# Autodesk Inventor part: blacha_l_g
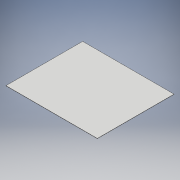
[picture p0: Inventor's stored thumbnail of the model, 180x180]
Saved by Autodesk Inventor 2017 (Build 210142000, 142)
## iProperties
Created: 2020-06
Part Number: blacha_l_g
Material: Generic
Document SubType Name: Modeling
Designer: WindowsX
Density: 1 g/cm^3
Appearance: Default
Author: WindowsX
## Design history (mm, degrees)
sketch "Szkic1"
  geometry: L1 (0, 0)-(1180, 0); L2 (1180, 0)-(1180, 990); L3 (1180, 990)-(0, 990); L4 (0, 990)-(0, 0)
  constraints: 8 end point, 2 parallel, 1 horizontal, 1 perpendicular
  dimensions: "d0" = 1180 distance of L2.end L3.end; "d1" = 990 distance of L1.start L3.end
extrude "Wyciągnięcie proste1" new body sketch "Szkic1" distance "d2" = 3; taper "d3" = 0 deg
node "Bryła1"
